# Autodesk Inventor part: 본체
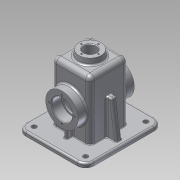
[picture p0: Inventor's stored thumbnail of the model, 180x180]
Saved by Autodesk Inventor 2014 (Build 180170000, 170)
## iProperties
Created: 2016-08
Part Number: 본체
Material: 알루미늄 6061
Document SubType Name: Modeling
Designer: user
Density: 2.71 g/cm^3
Appearance: 알루미늄 - 평지
Author: user
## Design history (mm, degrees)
sketch "스케치2"
  geometry: L1 (-57.5, -65)-(57.5, -65); L2 (57.5, -65)-(57.5, 65); L3 (57.5, 65)-(-57.5, 65); L4 (-57.5, 65)-(-57.5, -65); 3 further points
  constraints: 8 end point, 2 midpoint, 2 parallel, 1 horizontal, 1 horizontal alignment, 1 perpendicular, 1 vertical alignment
  dimensions: "d0" = 130 distance of L1.end L2.end; "d1" = 115 distance of L2.end L3.end
extrude "돌출1" new body sketch "스케치2" distance "d2" = 10; taper "d3" = 0 deg
sketch "스케치3"
  geometry: L1 (57.5, -65)-(-57.5, -65) reference; L2 (57.5, 65)-(57.5, -65) reference; L3 (-57.5, 65)-(57.5, 65) reference; L4 (-57.5, -65)-(-57.5, 65) reference; L5 (-52.5, 60)-(52.5, 60); L6 (52.5, 60)-(52.5, -60); L7 (52.5, -60)-(-52.5, -60); L8 (-52.5, -60)-(-52.5, 60); 1 further point
  constraints: 8 end point, 3 other
  dimensions: "d8" = 5 distance between parallel lines of L8 L4
extrude "돌출2" cut sketch "스케치3" distance "d6" = 3; taper "d7" = 0 deg
sketch "스케치4"
  geometry: L1 (-32.5, 32.5)-(32.5, 32.5); L2 (32.5, 32.5)-(32.5, -32.5); L3 (32.5, -32.5)-(-32.5, -32.5); L4 (-32.5, -32.5)-(-32.5, 32.5); 3 further points
  constraints: 8 end point, 2 midpoint, 2 parallel, 2 perpendicular, 1 horizontal, 1 horizontal alignment, 1 vertical alignment
  dimensions: "d11" = 65 distance of L1.start L1.end
extrude "돌출3" join sketch "스케치4" distance "d13" = 100; taper "d14" = 0 deg
sketch "스케치5"
  geometry: C1 r 20 at (0, 0); 1 further point
  constraints: 1 centre point, 1 coincident
  dimensions: "d15" = 40 diameter of C1
extrude "돌출4" join sketch "스케치5" distance "d16" = 10; taper "d17" = 0 deg
feature "면 기울기1" dims angle "d18" = 7 deg
sketch "스케치6"
  geometry: L1 (52.5, 3)-(52.5, 0) reference; L2 (52.5, 0)-(-52.5, 0) reference; L3 (-52.5, 0)-(-52.5, 3) reference; L4 (-52.5, 3)-(-57.5, 3) reference; L5 (-57.5, 3)-(-57.5, 10) reference; L6 (-57.5, 10)-(-32.5, 10) reference; L7 (-32.5, 10)-(-32.5, 110) reference; L8 (-32.5, 110)-(-20, 110) reference; L9 (-20, 110)-(-18.772, 120) reference; L10 (-18.772, 120)-(18.772, 120) reference; L11 (18.772, 120)-(20, 110) reference; L12 (20, 110)-(32.5, 110) reference; L13 (32.5, 110)-(32.5, 10) reference; L14 (32.5, 10)-(57.5, 10) reference; L15 (57.5, 10)-(57.5, 3) reference; L16 (57.5, 3)-(52.5, 3) reference; L17 (-49.5, 10)-(-41.068, 70); L18 (-41.068, 70)-(-32.5, 70); 1 further point
  constraints: 4 end point, 2 point on line, 1 perpendicular
  dimensions: "d19" = 8 horizontal distance of L4.end L17.start; "d20" = 8 deg angle of L5 L17; "d21" = 70 vertical distance of L2.end L17.end
feature "리브1" sketch "스케치6" dims "d22" = 1, "d23" = 10, "d24" = 0, "d25" = 0, "d26" = 1, "d27" = 1
sketch "스케치8"
  geometry: C1 r 27.5 at (0, 55); 1 further point
  constraints: 1 centre point
  dimensions: "d31" = 55 diameter of C1; "d32" = 55 distance of point (0, 0) C1.centre
extrude "돌출5" join sketch "스케치8" stored distance "d33" = 95; taper "d34" = 0 deg
sketch "스케치9"
  geometry: L1 (18.772, 120)-(20, 110) reference; L2 (20, 110)-(32.5, 110) reference; L3 (32.5, 110)-(32.5, 82.5) reference; L4 (32.5, 82.5)-(47.5, 82.5) reference; L5 (47.5, 82.5)-(47.5, 27.5) reference; L6 (47.5, 27.5)-(32.5, 27.5) reference; L7 (32.5, 27.5)-(32.5, 10) reference; L8 (32.5, 10)-(65, 10) reference; L9 (65, 10)-(65, 3) reference; L10 (65, 3)-(60, 3) reference; L11 (60, 3)-(60, 0) reference; L12 (60, 0)-(-60, 0) reference; L13 (-60, 0)-(-60, 3) reference; L14 (-60, 3)-(-65, 3) reference; L15 (-65, 3)-(-65, 10) reference; L16 (-65, 10)-(-32.5, 10) reference; L17 (-32.5, 10)-(-32.5, 27.5) reference; L18 (-32.5, 27.5)-(-47.5, 27.5) reference; L19 (-47.5, 27.5)-(-47.5, 82.5) reference; L20 (-47.5, 82.5)-(-32.5, 82.5) reference; L21 (-32.5, 82.5)-(-32.5, 110) reference; L22 (-32.5, 110)-(-20, 110) reference; L23 (-20, 110)-(-18.772, 120) reference; L24 (-18.772, 120)-(18.772, 120) reference; L25 (-27.5, 105)-(27.5, 105); L26 (27.5, 105)-(27.5, 0); L27 (27.5, 0)-(-27.5, 0); L28 (-27.5, 0)-(-27.5, 105); 1 further point
  constraints: 8 end point, 2 parallel, 1 horizontal, 1 perpendicular, 1 point on line
  dimensions: "d35" = 5 distance between parallel lines of L28 L21; "d36" = 5 distance between parallel lines of L3 L26; "d37" = 5 distance between parallel lines of L25 L22
extrude "돌출6" cut sketch "스케치9" stored distance "d38" = 55; taper "d39" = 0 deg
sketch "스케치10"
  geometry: L1 (18.772, 120)-(20, 110) reference; L2 (20, 110)-(32.5, 110) reference; L3 (32.5, 110)-(32.5, 82.5) reference; L4 (32.5, 82.5)-(47.5, 82.5) reference; L5 (47.5, 82.5)-(47.5, 27.5) reference; L6 (47.5, 27.5)-(32.5, 27.5) reference; L7 (32.5, 27.5)-(32.5, 10) reference; L8 (32.5, 10)-(65, 10) reference; L9 (65, 10)-(65, 3) reference; L10 (65, 3)-(60, 3) reference; L11 (60, 3)-(60, 0) reference; L12 (60, 0)-(27.5, 0) reference; L13 (27.5, 0)-(27.5, 105) reference; L14 (27.5, 105)-(-27.5, 105) reference; L15 (-27.5, 105)-(-27.5, 0) reference; L16 (-27.5, 0)-(-60, 0) reference; L17 (-60, 0)-(-60, 3) reference; L18 (-60, 3)-(-65, 3) reference; L19 (-65, 3)-(-65, 10) reference; L20 (-65, 10)-(-32.5, 10) reference; L21 (-32.5, 10)-(-32.5, 27.5) reference; L22 (-32.5, 27.5)-(-47.5, 27.5) reference; L23 (-47.5, 27.5)-(-47.5, 82.5) reference; L24 (-47.5, 82.5)-(-32.5, 82.5) reference; L25 (-32.5, 82.5)-(-32.5, 110) reference; L26 (-32.5, 110)-(-20, 110) reference; L27 (-20, 110)-(-18.772, 120) reference; L28 (-18.772, 120)-(18.772, 120) reference; L29 (-42.5, 10)-(-42.5, 30); 1 further point
  constraints: 2 end point, 1 perpendicular, 1 point on line
  dimensions: "d40" = 15 distance from line of L29.start L15; "d41" = 20 distance of L29.start L29.end
feature "리브2" sketch "스케치10" dims "d42" = 1, "d43" = 6, "d44" = 0, "d45" = 0, "d46" = 1, "d47" = 1
sketch "스케치11"
  geometry: C1 r 27.5 at (0, 0) reference; 1 further point
hole "구멍1" sketch "스케치11" at (0, 0) diameter "d48" = 30; stored, may be unused: countersink angle "d52" = 90 deg, drill point angle "d54" = 0 deg; dims "d49" = 6, "d50" = 35, "d51" = 17, "d53" = 8
sketch "스케치12"
  geometry: C1 r 18.772 at (0, 0) reference
hole "구멍2" sketch "스케치12" at (0, 0) diameter "d55" = 21; stored, may be unused: countersink angle "d59" = 90 deg, drill point angle "d61" = 0 deg; dims "d56" = 6, "d57" = 35, "d58" = 17, "d60" = 8
sketch "스케치13" dims "d62" = 42
  geometry: C1 r 17.5 at (0, 0) reference; C2 r 27.5 at (0, 0) reference; 6 further points
  constraints: 2 vertical alignment, 1 coincident, 7 other
  dimensions: "d65" = 360 deg dimension on C1.centre point (0, 21) (derived)
hole "구멍3" sketch "스케치13" at (0, 21), (-21, 0), (0, -21), (21, 0), (0, 0) diameter "d67" = 3.242; stored, may be unused: countersink angle "d71" = 90 deg, drill point angle "d73" = 118 deg; dims "d68" = 8, "d69" = 35, "d70" = 17, "d72" = 10
sketch "스케치14" dims "d74" = 29
  geometry: C1 r 10.5 at (0, 0) reference; C2 r 18.772 at (0, 0) reference; 5 further points
  constraints: 2 vertical alignment, 1 coincident, 7 other
  dimensions: "d77" = 360 deg dimension on C1.centre point (0, 14.5) (derived)
hole "구멍4" sketch "스케치14" at (0, 14.5), (-14.5, 0), (0, -14.5), (14.5, 0) diameter "d79" = 2.459; stored, may be unused: countersink angle "d83" = 90 deg, drill point angle "d85" = 118 deg; dims "d80" = 7, "d81" = 35, "d82" = 17, "d84" = 9
fillet "모깎기4" dims "d86" = 8
fillet "모깎기5" dims "d87" = 8
fillet "모깎기6" dims "d88" = 14
fillet "모깎기7" dims "d89" = 9
sketch "스케치15"
  geometry: A1 r 14 centre (-43.5, -51) between (-57.5, -51) and (-43.5, -65) reference; A2 r 14 centre (43.5, -51) between (43.5, -65) and (57.5, -51) reference; A3 r 14 centre (43.5, 51) between (57.5, 51) and (43.5, 65) reference; A4 r 14 centre (-43.5, 51) between (-43.5, 65) and (-57.5, 51) reference; 1 further point
hole "구멍5" sketch "스케치15" at (43.5, 51), (-43.5, 51), (-43.5, -51), (43.5, -51) diameter "d90" = 8; stored, may be unused: countersink angle "d94" = 90 deg, drill point angle "d96" = 0 deg; dims "d91" = 7, "d92" = 35, "d93" = 17, "d95" = 9
fillet "모깎기8" dims "d97" = 3
fillet "모깎기9" dims "d98" = 3
fillet "모깎기10" dims "d99" = 3
fillet "모깎기11" dims "d100" = 3
fillet "모깎기12" dims "d101" = 3
fillet "모깎기13" dims "d102" = 3
chamfer "모따기1" distance "d103" = 1; stored, may be unused: second distance "d104" = 2, angle "d105" = 45 deg
chamfer "모따기2" distance "d106" = 1; stored, may be unused: second distance "d107" = 2, angle "d108" = 45 deg
fillet "모깎기14" dims "d109" = 1
fillet "모깎기15" dims "d110" = 3
fillet "모깎기16" dims "d111" = 3
fillet "모깎기17" dims "d112" = 3
node "작업 평면1"
sketch "스케치16"
  geometry: L1 (5.728, -18)-(43.272, -18) reference; L2 (57, 0)-(57, 91) reference; 2 further points
  constraints: 1 other
  dimensions: "d115" = 32.5 distance from line of point (24.5, 8) L2; "d116" = 26 distance from line of point (24.5, 8) L1
feature "엠보싱1" sketch "스케치16" dims "d8" = 5, "d117" = 0.5, "d118" = 0
fillet "모깎기18" dims "d119" = 0.3
node "솔리드1"
mirror "대칭1"
mirror "대칭2"
mirror "대칭3"
mirror "대칭4"
node "절단 모서리 투영1"
node "절단 모서리 투영2"
node "절단 모서리 투영3"
